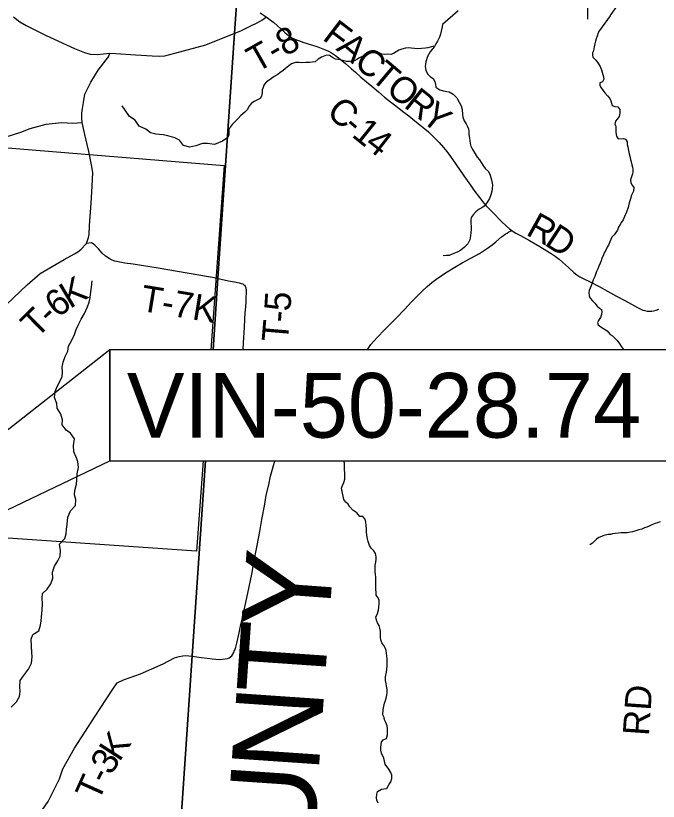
# Model space of a CAD drawing. Extents: x -8.2 to 34, y 0 to 22.
# Drawn here: x 6.05 to 7.441, y 17.043 to 18.744 of the extents above; entities that cross this region are included whole.
import ezdxf

# ---------------------------------------------------------------- set-up
doc = ezdxf.new("R2010")
doc.units = 0
for name, color, linetype in [('Default', 7, 'Continuous'), ('GM_X_Corporation', 7, 'Continuous'), ('GM_X_County_Road', 7, 'Continuous'), ('GM_X_County_Road_Text', 7, 'Continuous'), ('GM_X_County_Text', 7, 'Continuous'), ('GM_X_Minor_River', 7, 'Continuous'), ('GM_X_Township_Road', 7, 'Continuous'), ('GM_X_Township_Road_Text', 7, 'Continuous'), ('GM_X_Township_Text', 7, 'Continuous'), ('SN_P_Truss_Overhead', 7, 'Continuous')]:
    doc.layers.add(name, color=color, linetype=linetype)

msp = doc.modelspace()

# ---------------------------------------------------------------- linework, layer by layer
at = {"layer": 'Default'}
msp.add_lwpolyline([(6.2543, 18.0203), (5.4694, 17.4047), (6.2543, 17.7803)], close=True, dxfattribs=at)
at = {"layer": 'GM_X_Corporation'}
for points in [[(6.4774, 18.0203), (6.488, 18.1752), (6.5242, 18.7061), (6.5297, 18.7882), (6.5448, 18.981), (6.5455, 18.9878), (6.5461, 19.0017), (6.5463, 19.009), (6.5469, 19.0218), (6.548, 19.0467), (6.5487, 19.0617), (6.5495, 19.0821), (6.5503, 19.0966), (6.5514, 19.1092), (6.5523, 19.118), (6.5529, 19.1264), (6.5537, 19.1382), (6.5541, 19.1447), (6.5536, 19.1514), (6.5814, 19.5334), (6.6608, 20.6695), (6.6768, 20.9), (2.1, 20.9), (2.1, 14.1)], [(6.4559, 17.7803), (6.4419, 17.5848), (5.9698, 17.6173), (6.0241, 18.4583), (6.5013, 18.4191), (6.4729, 18.0203)], [(6.368, 16.4128), (6.4323, 17.3579), (6.4611, 17.7803)]]:
    msp.add_lwpolyline(points, dxfattribs=at)
at = {"layer": 'GM_X_County_Road'}
for points in [[(6.0456, 18.7413), (6.0593, 18.7306), (6.073, 18.7225), (6.116, 18.7004), (6.1773, 18.6724), (6.1992, 18.6639), (6.2117, 18.6605), (6.2263, 18.6595), (6.2538, 18.6624), (6.2667, 18.6621), (6.3096, 18.6588), (6.3454, 18.6564), (6.3618, 18.6557), (6.373, 18.6567), (6.395, 18.6624), (6.4618, 18.6805), (6.5244, 18.7056)], [(6.5798, 18.7497), (6.5924, 18.741), (6.6043, 18.7328), (6.6091, 18.729), (6.6166, 18.7225), (6.632, 18.7081), (6.6377, 18.7031), (6.6421, 18.6997), (6.648, 18.696), (6.6547, 18.6926), (6.6622, 18.6896), (6.6741, 18.6859), (6.6906, 18.6808), (6.7041, 18.6762), (6.7186, 18.6707), (6.7271, 18.667), (6.734, 18.663), (6.7422, 18.6575), (6.7492, 18.6524), (6.7639, 18.6402), (6.7775, 18.6284), (6.7859, 18.6211), (6.7975, 18.6108), (6.8094, 18.6007), (6.8213, 18.5908), (6.8355, 18.5788), (6.8488, 18.5675), (6.8618, 18.5569), (6.8701, 18.5504), (6.8904, 18.5351), (6.9011, 18.5266), (6.9143, 18.5161), (6.936, 18.4986), (6.9436, 18.4922), (6.9504, 18.486), (6.9593, 18.4774), (6.9673, 18.4689), (6.9763, 18.4586), (6.9833, 18.45), (6.9919, 18.4387), (7.0032, 18.4224), (7.0203, 18.3972), (7.0347, 18.3769), (7.0422, 18.3663), (7.0545, 18.3499), (7.0637, 18.3381), (7.069, 18.3319), (7.0824, 18.318), (7.102, 18.2981), (7.1128, 18.2877), (7.1194, 18.282), (7.1242, 18.2787), (7.1271, 18.2766), (7.133, 18.2731), (7.1434, 18.2675), (7.1623, 18.2568), (7.185, 18.2439), (7.2004, 18.2346), (7.2092, 18.2292), (7.2184, 18.2229), (7.2269, 18.2164), (7.2341, 18.2102), (7.2468, 18.1987), (7.2589, 18.1878), (7.2653, 18.1829), (7.2715, 18.1787), (7.2786, 18.1748), (7.2936, 18.1673), (7.3131, 18.1576), (7.3317, 18.1477), (7.3512, 18.1368), (7.3692, 18.1269), (7.3832, 18.119), (7.3964, 18.1122), (7.4021, 18.1093), (7.4082, 18.1064), (7.4125, 18.1052), (7.4176, 18.104), (7.4222, 18.1039), (7.4274, 18.1042), (7.4313, 18.1048), (7.4365, 18.1062), (7.4423, 18.1086)]]:
    msp.add_lwpolyline(points, dxfattribs=at)
at = {"layer": 'GM_X_Minor_River'}
for points in [[(7.289, 18.736), (7.2932, 19.1457), (7.2972, 19.1443), (7.311, 19.1517), (7.324, 19.1587), (7.3375, 19.1729), (7.3491, 19.1845), (7.3633, 19.1979), (7.3718, 19.2084), (7.3789, 19.2209), (7.392, 19.2347), (7.3959, 19.2449), (7.4001, 19.2665), (7.4014, 19.2779), (7.4023, 19.2881), (7.4025, 19.3022), (7.3997, 19.3174), (7.398, 19.3296), (7.4008, 19.3418), (7.4116, 19.3492), (7.4242, 19.3558), (7.4376, 19.3621)], [(7.366, 18.8033), (7.3664, 18.7976), (7.3669, 18.7927), (7.3662, 18.787), (7.361, 18.7748), (7.3569, 18.7698), (7.3508, 18.7636), (7.3471, 18.7587), (7.3422, 18.7514), (7.3389, 18.746), (7.3352, 18.7399)], [(7.0084, 18.7538), (6.9745, 18.7244)], [(7.3374, 18.7436), (7.3142, 18.7118), (7.3112, 18.7068), (7.3088, 18.6996), (7.3069, 18.6932), (7.3057, 18.6882), (7.3042, 18.6825), (7.3026, 18.6761), (7.3011, 18.6677), (7.2987, 18.6631), (7.2991, 18.6586), (7.2998, 18.6536), (7.3059, 18.6471), (7.3104, 18.6418), (7.3157, 18.6334), (7.3183, 18.6265), (7.3228, 18.6113), (7.3235, 18.6063), (7.3208, 18.6002), (7.3151, 18.5984), (7.3151, 18.5923), (7.3181, 18.5877), (7.3215, 18.5827), (7.326, 18.577), (7.3317, 18.5705), (7.3362, 18.5644), (7.3385, 18.5594), (7.34, 18.5545), (7.3418, 18.5495), (7.3471, 18.5472), (7.354, 18.5464), (7.3585, 18.5407), (7.3585, 18.5327), (7.3565, 18.5255), (7.3527, 18.5198), (7.3485, 18.5152), (7.3477, 18.5091), (7.3492, 18.5046), (7.3495, 18.4985), (7.3495, 18.4905), (7.3506, 18.4825), (7.3547, 18.4771), (7.3661, 18.4779), (7.3707, 18.4763), (7.3741, 18.4706), (7.3744, 18.4645), (7.3752, 18.4595), (7.3766, 18.4515), (7.3785, 18.4443), (7.3796, 18.4393), (7.3815, 18.4325), (7.383, 18.4272), (7.3844, 18.4207), (7.3856, 18.4161), (7.3863, 18.4115), (7.3863, 18.4058), (7.3855, 18.4013), (7.3824, 18.3929), (7.3812, 18.388), (7.3823, 18.3819), (7.385, 18.3769), (7.3884, 18.3716), (7.3875, 18.364), (7.3837, 18.3548), (7.3814, 18.3469), (7.3787, 18.3385), (7.3759, 18.3286), (7.3725, 18.3184), (7.3686, 18.3089), (7.3651, 18.3017), (7.3621, 18.2967), (7.359, 18.2914), (7.3552, 18.2857), (7.3528, 18.2797), (7.3456, 18.2694), (7.341, 18.2641), (7.3363, 18.2539), (7.3336, 18.247), (7.331, 18.2425), (7.3279, 18.2364), (7.3244, 18.2303), (7.3225, 18.2258), (7.3194, 18.2182), (7.3175, 18.2132), (7.3155, 18.2079), (7.3125, 18.2015), (7.3109, 18.1958), (7.3078, 18.1901), (7.3059, 18.1855), (7.304, 18.1794), (7.3005, 18.1719), (7.2982, 18.1646), (7.2959, 18.1589), (7.2936, 18.154), (7.292, 18.1491), (7.2912, 18.1445), (7.292, 18.1373), (7.2938, 18.1323), (7.2987, 18.1266), (7.3044, 18.1216), (7.3093, 18.1147)], [(6.9745, 18.7248), (6.9737, 18.7194), (6.9717, 18.7103), (6.9701, 18.7039), (6.9678, 18.6971), (6.9631, 18.6888), (6.9597, 18.6827), (6.9566, 18.677), (6.9523, 18.6718), (6.9477, 18.6657), (6.9415, 18.6552), (6.938, 18.6434), (6.9364, 18.6339), (6.9378, 18.6259), (6.9419, 18.6175), (6.9483, 18.6114), (6.954, 18.6079), (6.9573, 18.601), (6.9588, 18.5946), (6.9595, 18.5892), (6.9682, 18.5834), (6.9765, 18.5807), (6.9837, 18.5795), (6.989, 18.5787), (6.9974, 18.574), (7.0056, 18.5656), (7.0105, 18.5564), (7.0146, 18.5484), (7.0168, 18.5404), (7.0178, 18.5301), (7.0185, 18.524), (7.0211, 18.516), (7.0256, 18.5095), (7.0286, 18.5038), (7.0304, 18.4984), (7.0312, 18.4931), (7.0315, 18.4863), (7.0325, 18.4783), (7.0336, 18.4729), (7.0343, 18.4672), (7.0358, 18.4611), (7.0384, 18.4558), (7.0425, 18.4481), (7.0496, 18.4371), (7.0541, 18.4313), (7.0582, 18.4256), (7.0612, 18.4202), (7.0669, 18.4129), (7.0736, 18.4064), (7.0774, 18.3984), (7.0803, 18.3885), (7.0825, 18.3774), (7.082, 18.3691), (7.0808, 18.3638), (7.0788, 18.3562), (7.0761, 18.3482), (7.0703, 18.3388), (7.0646, 18.3316), (7.0592, 18.3275), (7.0535, 18.3245), (7.0462, 18.3193), (7.0408, 18.3129), (7.0366, 18.3065), (7.0354, 18.3011), (7.0357, 18.2939), (7.0364, 18.2878), (7.0363, 18.2806), (7.0355, 18.2742), (7.0347, 18.2673), (7.0331, 18.2586), (7.0288, 18.2499), (7.0215, 18.2424), (7.0142, 18.2364), (7.0077, 18.2326), (7.0024, 18.23), (6.9955, 18.2271), (6.9883, 18.2249), (6.9826, 18.2242), (6.9757, 18.2235)], [(6.9554, 18.6778), (6.9477, 18.6756), (6.9424, 18.6741), (6.9371, 18.673), (6.9291, 18.6724), (6.9211, 18.6721), (6.9139, 18.6729), (6.9067, 18.673), (6.8999, 18.6738), (6.8941, 18.6731), (6.8865, 18.6709), (6.8797, 18.6687), (6.8739, 18.6653), (6.8678, 18.6616), (6.8621, 18.6597), (6.856, 18.6602), (6.8492, 18.6599), (6.8431, 18.6607), (6.8374, 18.663), (6.8321, 18.6635), (6.8268, 18.6631), (6.8215, 18.6632), (6.815, 18.6617), (6.8085, 18.6595), (6.8005, 18.6554), (6.7948, 18.6524), (6.789, 18.6491), (6.7837, 18.6457), (6.7784, 18.645), (6.7727, 18.6447), (6.7666, 18.6444), (6.7613, 18.6456), (6.7526, 18.6479), (6.7427, 18.6492), (6.7359, 18.653), (6.7299, 18.6577), (6.723, 18.6581), (6.712, 18.6537), (6.7051, 18.6492), (6.6982, 18.6439), (6.6917, 18.6429), (6.6864, 18.6425), (6.6784, 18.6422), (6.6697, 18.6419), (6.6636, 18.6424), (6.6556, 18.6421), (6.6472, 18.6391), (6.6415, 18.635), (6.6346, 18.6294), (6.6285, 18.6245), (6.6227, 18.6204), (6.6174, 18.6166), (6.6101, 18.6118), (6.604, 18.608), (6.5986, 18.6043), (6.5933, 18.6002), (6.5883, 18.5945), (6.5856, 18.5885), (6.5836, 18.5832), (6.5836, 18.5767), (6.5827, 18.5695), (6.5796, 18.5642), (6.5667, 18.5579), (6.5609, 18.5541), (6.5548, 18.547), (6.5517, 18.5409), (6.5459, 18.5349), (6.5379, 18.5278), (6.5313, 18.5202), (6.524, 18.5135), (6.5191, 18.5078), (6.5144, 18.5022), (6.5117, 18.4965), (6.5117, 18.4908), (6.5116, 18.4851), (6.5085, 18.4794), (6.5028, 18.4757), (6.4979, 18.4718)], [(6.4979, 18.4718), (6.4809, 18.4651), (6.4652, 18.4669), (6.4546, 18.4673), (6.4403, 18.462), (6.4274, 18.4593), (6.4137, 18.4623), (6.4046, 18.4741), (6.3944, 18.4794), (6.3796, 18.4835), (6.3694, 18.4854), (6.3539, 18.4869), (6.3417, 18.4903), (6.3319, 18.4982), (6.3175, 18.5047), (6.3091, 18.5172), (6.2962, 18.5255), (6.2875, 18.5388), (6.281, 18.5482)], [(6.169, 17.8397), (6.1592, 17.8465), (6.1508, 17.8582), (6.1516, 17.8685), (6.1478, 17.881), (6.1402, 17.8942), (6.139, 17.9045), (6.1345, 17.917), (6.1356, 17.9303), (6.1401, 17.9413), (6.1458, 17.9515), (6.1507, 17.9625), (6.1515, 17.972), (6.1511, 17.9826), (6.1526, 17.994), (6.1575, 18.0058), (6.1631, 18.0175), (6.1643, 18.0281), (6.1718, 18.041), (6.1775, 18.0539), (6.1813, 18.0646), (6.1866, 18.0763), (6.1922, 18.0866), (6.1994, 18.0991), (6.2054, 18.1135), (6.2092, 18.1238), (6.2115, 18.1333), (6.213, 18.1461), (6.2145, 18.156), (6.2156, 18.1697)], [(7.3093, 18.1147), (7.3139, 18.1105), (7.3184, 18.1074), (7.3195, 18.1025), (7.3187, 18.0972), (7.316, 18.0903), (7.3122, 18.0839), (7.3099, 18.0793), (7.311, 18.0748), (7.3167, 18.0705), (7.3311, 18.0613), (7.3375, 18.0537), (7.342, 18.0506), (7.3481, 18.0449), (7.3526, 18.0403), (7.3579, 18.0323), (7.3617, 18.0269), (7.3658, 18.0208), (7.366, 18.0203)], [(6.0402, 17.2471), (6.0516, 17.2581), (6.0584, 17.2703), (6.0595, 17.2805), (6.0591, 17.2908), (6.0599, 17.3044), (6.067, 17.3147), (6.078, 17.3291), (6.0844, 17.3424), (6.0856, 17.356), (6.0852, 17.3655), (6.0844, 17.3792), (6.084, 17.3943), (6.087, 17.4042), (6.1003, 17.4118), (6.104, 17.4243), (6.1052, 17.4338), (6.1078, 17.4577), (6.1081, 17.4695), (6.1077, 17.4831), (6.1085, 17.493), (6.1183, 17.5021), (6.1263, 17.5142), (6.1304, 17.526), (6.13, 17.5393), (6.1342, 17.5518), (6.1414, 17.5639), (6.1463, 17.5734), (6.147, 17.5863), (6.1447, 17.6), (6.1564, 17.6121), (6.1595, 17.622), (6.1602, 17.6322), (6.1613, 17.6425), (6.1632, 17.6584), (6.1689, 17.672), (6.1798, 17.6831), (6.1802, 17.6967), (6.1775, 17.7066), (6.1783, 17.7161), (6.1817, 17.7297), (6.1828, 17.7392), (6.1835, 17.7521), (6.1858, 17.7654), (6.1847, 17.7783), (6.1812, 17.7881), (6.1763, 17.7999), (6.1755, 17.8131), (6.1774, 17.8275), (6.169, 17.8397)], [(6.8527, 17.3225), (6.8543, 17.3354), (6.8544, 17.3407), (6.8545, 17.3506), (6.8534, 17.3578), (6.8527, 17.3635), (6.852, 17.3696), (6.8501, 17.3754), (6.8475, 17.3807), (6.843, 17.3864), (6.8408, 17.3926), (6.8401, 17.3986), (6.8398, 17.4062), (6.8399, 17.4116), (6.8388, 17.418), (6.8373, 17.4238), (6.8336, 17.4295), (6.8313, 17.4352), (6.8299, 17.4424), (6.8326, 17.4477), (6.8354, 17.4568), (6.8366, 17.4633), (6.8374, 17.4709), (6.8371, 17.4777), (6.8349, 17.4838), (6.8307, 17.4896), (6.8308, 17.4949), (6.8301, 17.5014), (6.8302, 17.5147), (6.8299, 17.5215), (6.8296, 17.5276), (6.8289, 17.5348), (6.8282, 17.5401), (6.8283, 17.5481), (6.8287, 17.5542), (6.8299, 17.5606), (6.8303, 17.5671), (6.8304, 17.5724), (6.8289, 17.5797), (6.8256, 17.585), (6.8199, 17.5911), (6.8162, 17.5969), (6.8136, 17.6057), (6.8118, 17.6114), (6.8103, 17.6194), (6.81, 17.6266), (6.8097, 17.6319), (6.8086, 17.6403), (6.8079, 17.6475), (6.8065, 17.654), (6.8016, 17.6594), (6.7955, 17.6598), (6.7888, 17.6675), (6.7801, 17.6736), (6.7733, 17.6806), (6.7699, 17.6863), (6.7647, 17.6909), (6.7605, 17.6966), (6.7591, 17.7039), (6.7576, 17.7104), (6.7558, 17.7206), (6.7574, 17.7267), (6.7609, 17.7331), (6.7625, 17.7403), (6.7626, 17.7544), (6.7623, 17.7609), (6.7624, 17.7673), (6.7617, 17.7749), (6.7606, 17.7803)], [(7.4455, 17.6483), (7.4394, 17.646), (7.4344, 17.6441), (7.4276, 17.6415), (7.4215, 17.6389), (7.4165, 17.6362), (7.4115, 17.6351), (7.4058, 17.6325), (7.399, 17.6306), (7.3929, 17.6284), (7.3856, 17.6265), (7.3811, 17.6257), (7.3738, 17.6246), (7.3678, 17.6243), (7.3613, 17.6243), (7.3556, 17.6236), (7.348, 17.6229), (7.3426, 17.6221), (7.3377, 17.6203), (7.3327, 17.6203), (7.3236, 17.6188), (7.3183, 17.6166), (7.3126, 17.6143), (7.308, 17.6105), (7.3034, 17.6064), (7.2988, 17.6018), (7.2934, 17.598)], [(6.8351, 17.0388), (6.8321, 17.0453), (6.8314, 17.0506), (6.8319, 17.0586), (6.8338, 17.0643), (6.8419, 17.0691), (6.8472, 17.0698), (6.8537, 17.0709), (6.8583, 17.0785), (6.8626, 17.0856), (6.8645, 17.0925), (6.8646, 17.0997), (6.8624, 17.1054), (6.8579, 17.1127), (6.8504, 17.1238), (6.8471, 17.1363), (6.8419, 17.1474), (6.8408, 17.1539), (6.8409, 17.1603), (6.8421, 17.171), (6.8459, 17.1763), (6.8532, 17.1788), (6.8552, 17.1868), (6.8553, 17.2001), (6.8542, 17.2066), (6.8512, 17.2134), (6.849, 17.2192), (6.8476, 17.2245), (6.8453, 17.2302), (6.8458, 17.2409), (6.847, 17.2492), (6.849, 17.2557), (6.8506, 17.261), (6.8525, 17.2666), (6.8537, 17.2731), (6.8545, 17.2784), (6.8542, 17.2852), (6.8531, 17.2921), (6.8521, 17.2982), (6.8506, 17.3043), (6.8511, 17.3126), (6.8527, 17.3225)]]:
    msp.add_lwpolyline(points, dxfattribs=at)
at = {"layer": 'GM_X_Township_Road'}
for points in [[(6.5244, 18.7056), (6.5373, 18.7112), (6.5465, 18.7153), (6.5596, 18.7216), (6.5731, 18.7283), (6.5833, 18.7341), (6.5878, 18.7374), (6.591, 18.7399), (6.5924, 18.741)], [(6.0131, 18.4761), (6.0613, 18.4915), (6.0818, 18.4998), (6.116, 18.5091), (6.149, 18.5121), (6.1737, 18.5113), (6.1938, 18.5122), (6.1931, 18.5219), (6.1936, 18.5324), (6.1951, 18.543), (6.1971, 18.556), (6.2001, 18.574), (6.2129, 18.5999), (6.2287, 18.626), (6.2513, 18.6545), (6.2538, 18.6624)], [(6.4882, 18.1746), (6.3584, 18.1973), (6.3044, 18.2059), (6.2863, 18.2083), (6.2651, 18.2124), (6.2588, 18.2148), (6.2522, 18.2179), (6.2447, 18.2228), (6.2374, 18.2294), (6.2293, 18.2392), (6.2215, 18.2472), (6.2177, 18.2501), (6.2141, 18.2518), (6.2031, 18.2503), (6.2075, 18.2634), (6.2089, 18.2699), (6.21, 18.2893), (6.2138, 18.3376), (6.2157, 18.3746), (6.2171, 18.4045), (6.2146, 18.4206), (6.2084, 18.45), (6.2001, 18.4866), (6.1938, 18.5122)], [(6.8106, 18.0203), (6.813, 18.0233), (6.8193, 18.0318), (6.8256, 18.0394), (6.8333, 18.0481), (6.8483, 18.0637), (6.865, 18.0806), (6.8736, 18.0891), (6.8925, 18.1087), (6.9073, 18.1241), (6.9174, 18.1344), (6.9235, 18.1407), (6.9259, 18.1432), (6.9309, 18.1478), (6.9413, 18.1574), (6.9512, 18.1659), (6.96, 18.1728), (6.9712, 18.1807), (6.981, 18.1872), (7.0044, 18.2013), (7.0168, 18.2084), (7.0249, 18.2129), (7.0449, 18.2239), (7.054, 18.2292), (7.0629, 18.2347), (7.0737, 18.2417), (7.0814, 18.2474), (7.0895, 18.2543), (7.1019, 18.2648), (7.1062, 18.2682), (7.1099, 18.2708), (7.1139, 18.2731), (7.1182, 18.2755), (7.1215, 18.2773), (7.1242, 18.2787)], [(5.9869, 17.9211), (5.9877, 17.9491), (5.9901, 17.9756), (5.9922, 18.0304), (5.9939, 18.062), (5.9943, 18.075), (5.9974, 18.0812), (6.0016, 18.0891), (6.0304, 18.1182), (6.075, 18.1612), (6.1033, 18.1855), (6.1554, 18.2157), (6.1775, 18.2279), (6.1846, 18.2327), (6.1915, 18.2375), (6.2031, 18.2503)], [(6.4882, 18.1746), (6.5112, 18.1698), (6.5242, 18.1672), (6.534, 18.1652), (6.5382, 18.1641), (6.5416, 18.1629), (6.5437, 18.162), (6.5455, 18.1603), (6.5467, 18.1584), (6.5476, 18.1568), (6.5482, 18.1548), (6.5486, 18.1529), (6.5488, 18.1507), (6.549, 18.1452), (6.5485, 18.1321), (6.5482, 18.1241), (6.5475, 18.1136), (6.5464, 18.1001), (6.5456, 18.0871), (6.5446, 18.0685), (6.5426, 18.0357), (6.5419, 18.0203)], [(6.4325, 17.3574), (6.4525, 17.3546), (6.465, 17.3528), (6.4755, 17.3515), (6.4835, 17.3509), (6.4922, 17.3504), (6.4978, 17.3506), (6.5037, 17.3512), (6.5086, 17.3523), (6.512, 17.3537), (6.5151, 17.3558), (6.5178, 17.3583), (6.52, 17.3613), (6.5222, 17.3651), (6.5234, 17.3678), (6.5244, 17.37), (6.5266, 17.3771), (6.5295, 17.3885), (6.5339, 17.4079), (6.5371, 17.4224), (6.5403, 17.4376), (6.5469, 17.4673), (6.5528, 17.494), (6.5614, 17.5348), (6.5645, 17.5512), (6.5673, 17.5659), (6.5697, 17.5787), (6.5731, 17.597), (6.5787, 17.6269), (6.583, 17.6533), (6.5892, 17.6862), (6.5928, 17.7057), (6.5979, 17.7285), (6.602, 17.7467), (6.606, 17.762), (6.6081, 17.77), (6.6105, 17.7774), (6.6117, 17.7803)], [(6.0583, 16.983), (6.0777, 16.9924), (6.0884, 16.9999), (6.092, 17.0036), (6.0988, 17.0119), (6.1203, 17.0429), (6.1357, 17.0732), (6.1452, 17.092), (6.1519, 17.1136), (6.1775, 17.158), (6.2225, 17.2274), (6.259, 17.2839), (6.27, 17.2996), (6.2833, 17.3062), (6.3202, 17.3194), (6.3695, 17.3409), (6.3937, 17.3537), (6.4039, 17.3568), (6.4119, 17.3582), (6.4181, 17.3587), (6.4325, 17.3574)]]:
    msp.add_lwpolyline(points, dxfattribs=at)
at = {"layer": 'GM_X_Township_Text'}
for points in [[(6.6768, 20.9), (6.6608, 20.6695), (6.5814, 19.5334), (6.5536, 19.1514), (6.5541, 19.1447), (6.5537, 19.1382), (6.5529, 19.1264), (6.5523, 19.118), (6.5514, 19.1092), (6.5503, 19.0966), (6.5495, 19.0821), (6.5487, 19.0617), (6.548, 19.0467), (6.5469, 19.0218), (6.5463, 19.009), (6.5461, 19.0017), (6.5455, 18.9878), (6.5448, 18.981), (6.5297, 18.7882), (6.5242, 18.7061), (6.488, 18.1752), (6.4774, 18.0203)], [(6.4611, 17.7803), (6.4323, 17.3579), (6.368, 16.4128), (6.3333, 15.9036), (6.2987, 15.5287)]]:
    msp.add_lwpolyline(points, dxfattribs=at)
at = {"layer": 'SN_P_Truss_Overhead'}
msp.add_lwpolyline([(7.6168, 18.0203), (6.2543, 18.0203), (6.2543, 17.7803), (7.6168, 17.7803)], close=True, dxfattribs=at)

# ---------------------------------------------------------------- texts
at = {"layer": 'GM_X_County_Road_Text'}
for s, height, rotation, p in [('F', 0.0568, 322.7034, (6.712, 18.6933)), ('A', 0.0568, 319.6907, (6.7419, 18.6706)), ('C', 0.0568, 319.2124, (6.7799, 18.6383)), ('T', 0.0568, 319.8082, (6.8157, 18.6074)), ('O', 0.0568, 320.8584, (6.8491, 18.5793)), ('R', 0.0568, 321.3344, (6.8883, 18.5474)), ('C', 0.0568, 318.5361, (6.7204, 18.5312)), ('Y', 0.0568, 321.0168, (6.9246, 18.5183)), ('-', 0.0568, 320.0607, (6.7566, 18.4992)), ('1', 0.0568, 321.1217, (6.7754, 18.4835)), ('4', 0.0568, 321.9516, (6.8033, 18.461)), ('R', 0.0568, 330.9067, (7.1527, 18.2707)), ('D', 0.0568, 327.0323, (7.1927, 18.2485)), ('RD', 0.05682, 86.0551, (7.4211, 17.1838))]:
    msp.add_text(s, height=height, rotation=rotation, dxfattribs=at).set_placement(p)
at = {"layer": 'GM_X_County_Text'}
for s, rotation, p in [('Y', 85.8022, (6.7272, 17.4106)), ('T', 86.0344, (6.7174, 17.2695)), ('N', 86.066, (6.7059, 17.1024)), ('U', 86.0747, (6.6944, 16.9353))]:
    msp.add_text(s, height=0.1894, rotation=rotation, dxfattribs=at).set_placement(p)
at = {"layer": 'GM_X_Township_Road_Text'}
for s, height, rotation, p in [('T-8', 0.05682, 29.5674, (6.5714, 18.6191)), ('K', 0.0568, 30.8438, (6.1673, 18.1084)), ('T-7K', 0.05682, 350.587, (6.3178, 18.1052)), ('6', 0.0568, 37.7463, (6.1411, 18.088)), ('5', 0.0568, 86.3891, (6.6448, 18.1027)), ('T', 0.0568, 44.4606, (6.0953, 18.0432)), ('-', 0.0568, 43.8572, (6.1255, 18.0729)), ('-', 0.0568, 85.3148, (6.6428, 18.0783)), ('T', 0.0568, 85.16, (6.6392, 18.0358)), ('K', 0.0568, 57.199, (6.2747, 17.1268)), ('3', 0.0568, 58.0795, (6.2565, 17.0976)), ('-', 0.0568, 62.0952, (6.2462, 17.078)), ('T', 0.0568, 65.8308, (6.2292, 17.0402))]:
    msp.add_text(s, height=height, rotation=rotation, dxfattribs=at).set_placement(p)
at = {"layer": 'SN_P_Truss_Overhead'}
msp.add_text('VIN-50-28.74', height=0.14, dxfattribs=at).set_placement((6.2908, 17.8303))

doc.saveas('drawing.dxf')
